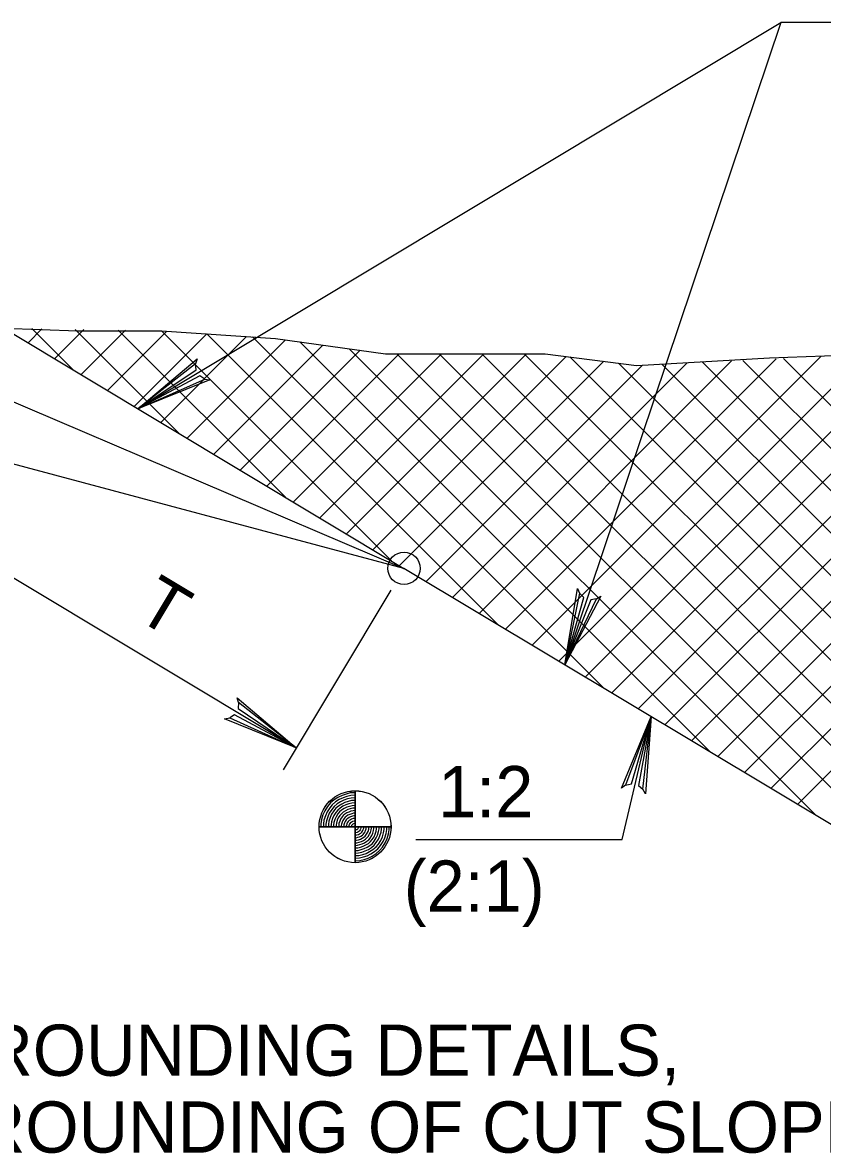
# Model space of a CAD drawing. Extents: x 240 to 1147, y 662 to 1256.
# Drawn here: x 760.7 to 810.7, y 1108.8 to 1179.4 of the extents above; entities that cross this region are included whole.
import ezdxf

# ---------------------------------------------------------------- set-up
doc = ezdxf.new("R2010")
doc.units = 0
for name, color, linetype in [('1', 7, 'Continuous'), ('2', 7, 'Continuous'), ('3', 7, 'Continuous')]:
    doc.layers.add(name, color=color, linetype=linetype)

msp = doc.modelspace()

# ---------------------------------------------------------------- linework, layer by layer
at = {"layer": '1'}
for points in [[(772.0915, 1157.151125), (771.779, 1157.346875), (767.906, 1155.301125), (772.0915, 1157.151125), (772.3955, 1157.101125), (767.906, 1155.301125), (771.53925, 1157.736375), (771.508, 1158.096875), (767.906, 1155.301125), (771.608, 1158.409375), (771.508, 1158.096875)], [(796.54975, 1143.430125), (796.183, 1143.373875), (794.56225, 1139.307375), (796.54975, 1143.430125), (796.81225, 1143.586375), (794.56225, 1139.307375), (795.74975, 1143.517625), (795.4915, 1143.771875), (794.56225, 1139.307375), (795.36425, 1144.073875), (795.4915, 1143.771875)], [(774.1955, 1136.942625), (774.1705, 1136.573875), (777.7955, 1134.117625), (774.1955, 1136.942625), (774.09775, 1137.234375), (777.7955, 1134.117625), (773.93925, 1136.180125), (773.63525, 1135.984375), (777.7955, 1134.117625), (773.31225, 1135.923875), (773.63525, 1135.984375)], [(798.36425, 1131.780125), (798.72275, 1131.869875), (799.958, 1136.069875), (798.36425, 1131.780125), (798.1165, 1131.598875), (799.958, 1136.069875), (799.1685, 1131.769875), (799.44775, 1131.538625), (799.958, 1136.069875), (799.604, 1131.251125), (799.44775, 1131.538625)]]:
    msp.add_lwpolyline(points, dxfattribs=at)
at = {"layer": '2'}
for p, q in [((784.52275, 1145.330125), (728.27275, 1160.330125)), ((759.52275, 1160.330125), (784.52275, 1145.330125)), ((761.03925, 1159.421875), (761.91025, 1160.292625)), ((763.86025, 1157.730125), (761.28725, 1160.303125)), ((762.69775, 1158.426125), (764.5185, 1160.248875)), ((770.48925, 1153.751125), (763.983, 1160.257375)), ((764.354, 1157.432375), (767.12675, 1160.205125)), ((766.01225, 1156.438625), (769.7185, 1160.144875)), ((777.1165, 1149.773875), (766.679, 1160.213625)), ((767.6685, 1155.442625), (772.204, 1159.978125)), ((783.74775, 1145.796875), (769.37475, 1160.167625)), ((790.37675, 1141.819875), (772.2185, 1159.976125)), ((769.32675, 1154.448875), (774.68725, 1159.811375)), ((770.983, 1153.455125), (777.129, 1159.601125)), ((772.6415, 1152.461375), (779.456, 1159.276125)), ((797.004, 1137.842625), (775.06225, 1159.786375)), ((803.63525, 1133.863625), (778.02275, 1159.476125)), ((807.4435, 1131.578125), (835.32475, 1159.461375)), ((809.09975, 1130.584375), (838.2685, 1159.751125)), ((774.29775, 1151.465625), (781.783, 1158.951125)), ((775.956, 1150.471875), (784.21225, 1158.728125)), ((777.61225, 1149.478125), (786.86425, 1158.728125)), ((779.2705, 1148.482375), (789.51425, 1158.728125)), ((780.92675, 1147.488625), (792.1665, 1158.728125)), ((810.26425, 1129.886375), (781.104, 1159.044875)), ((782.58525, 1146.494875), (794.654, 1158.563625)), ((816.8935, 1125.909375), (784.07275, 1158.728125)), ((823.5205, 1121.932375), (786.72475, 1158.728125)), ((827.21225, 1120.892625), (789.37675, 1158.728125)), ((829.86425, 1120.892625), (792.029, 1158.728125)), ((792.529, 1140.528125), (810.554, 1158.555125)), ((794.18525, 1139.534375), (813.33725, 1158.686375)), ((832.5165, 1120.892625), (794.87275, 1158.534375)), ((795.8435, 1138.538625), (815.97475, 1158.671875)), ((797.49975, 1137.544875), (818.5415, 1158.586375)), ((799.158, 1136.551125), (821.11025, 1158.503125)), ((805.78725, 1132.573875), (832.054, 1158.840625)), ((784.2415, 1145.498875), (797.006, 1158.265625)), ((785.89975, 1144.505125), (799.4205, 1158.026125)), ((787.556, 1143.511375), (802.204, 1158.159375)), ((789.21425, 1142.517625), (804.98725, 1158.290625)), ((790.8705, 1141.521875), (807.7705, 1158.421875)), ((835.1685, 1120.892625), (797.91025, 1158.151125)), ((837.8185, 1120.892625), (800.629, 1158.084375)), ((800.81425, 1135.555125), (823.679, 1158.419875)), ((802.47275, 1134.561375), (826.2455, 1158.336375)), ((840.4705, 1120.892625), (803.16025, 1158.203125)), ((804.129, 1133.567625), (828.81425, 1158.253125)), ((843.12275, 1120.892625), (805.6915, 1158.323875)), ((845.77475, 1120.892625), (808.22275, 1158.444875)), ((758.08525, 1156.594875), (784.52275, 1145.330125)), ((777.7955, 1134.117625), (752.7955, 1149.117625)), ((825.254, 1120.892625), (784.52275, 1145.330125)), ((783.69975, 1143.959375), (776.97275, 1132.746875)), ((781.46425, 1126.944875), (781.46425, 1131.434375)), ((781.46425, 1131.432375), (781.46425, 1126.942625)), ((781.4665, 1126.944875), (781.4665, 1131.434375)), ((781.4665, 1131.432375), (781.4665, 1126.942625)), ((783.71025, 1129.188625), (779.2185, 1129.188625)), ((783.71025, 1129.188625), (779.2185, 1129.188625)), ((779.2205, 1129.188625), (783.71025, 1129.188625)), ((779.2205, 1129.188625), (783.71025, 1129.188625))]:
    msp.add_line(p, q, dxfattribs=at)
for points in [[(767.906, 1155.301125), (808.05175, 1179.421875)], [(811.401, 1179.421875), (810.55175, 1179.421875), (808.05175, 1179.421875), (794.56225, 1139.307375)], [(759.52275, 1160.330125), (764.156, 1160.167625), (769.37675, 1160.167625), (776.4955, 1159.688625), (783.37675, 1158.728125), (793.3415, 1158.728125), (799.03725, 1158.009375), (807.3415, 1158.488625), (814.22275, 1158.728125), (820.3915, 1158.488625), (828.933, 1158.248875), (836.52675, 1159.688625), (843.1705, 1159.928125), (851.47475, 1159.448875), (864.05175, 1163.528125), (875.679, 1161.848875), (884.933, 1160.167625), (894.89775, 1159.448875), (899.406, 1159.448875), (912.2185, 1160.648875), (921.47275, 1162.328125), (925.98525, 1160.330125)], [(785.259, 1128.382375), (798.15175, 1128.382375), (799.958, 1136.069875)], [(781.458, 1131.313625), (781.1685, 1131.296875), (780.90175, 1131.228125), (780.654, 1131.148875), (780.39975, 1131.023875), (780.156, 1130.867625), (779.929, 1130.676125), (779.75175, 1130.461375), (779.57675, 1130.192625), (779.46025, 1129.930125), (779.3685, 1129.638625), (779.329, 1129.380125), (779.32475, 1129.180125)], [(781.458, 1131.155125), (781.1935, 1131.138625), (780.9455, 1131.073875), (780.71425, 1130.998875), (780.47675, 1130.884375), (780.24975, 1130.740625), (780.0415, 1130.565625), (779.881, 1130.367625), (779.7165, 1130.117625), (779.61025, 1129.873875), (779.52475, 1129.603125), (779.48925, 1129.365625), (779.48525, 1129.180125)], [(781.458, 1130.994875), (781.2185, 1130.980125), (780.9915, 1130.921875), (780.77275, 1130.851125), (780.556, 1130.744875), (780.3455, 1130.611375), (780.156, 1130.453125), (780.01025, 1130.271875), (779.858, 1130.040625), (779.76025, 1129.817625), (779.681, 1129.567625), (779.64775, 1129.351125), (779.6435, 1129.180125)], [(781.458, 1130.834375), (781.2435, 1130.821875), (781.03525, 1130.767625), (780.833, 1130.703125), (780.633, 1130.605125), (780.43925, 1130.482375), (780.2705, 1130.340625), (780.13925, 1130.178125), (779.99775, 1129.965625), (779.91025, 1129.761375), (779.83725, 1129.530125), (779.806, 1129.338625), (779.804, 1129.180125)], [(781.458, 1130.673875), (781.2685, 1130.663625), (781.079, 1130.615625), (780.8935, 1130.555125), (780.71025, 1130.467625), (780.53525, 1130.353125), (780.38525, 1130.228125), (780.2685, 1130.084375), (780.13925, 1129.888625), (780.058, 1129.705125), (779.9915, 1129.494875), (779.9665, 1129.323875), (779.96225, 1129.180125)], [(781.458, 1130.515625), (781.2935, 1130.505125), (781.12275, 1130.461375), (780.95175, 1130.405125), (780.78925, 1130.328125), (780.629, 1130.226125), (780.49975, 1130.115625), (780.3955, 1129.990625), (780.279, 1129.811375), (780.208, 1129.648875), (780.14775, 1129.457375), (780.12475, 1129.309375), (780.12275, 1129.180125)], [(781.458, 1130.355125), (781.3185, 1130.346875), (781.1665, 1130.307375), (781.01225, 1130.257375), (780.8665, 1130.188625), (780.72275, 1130.096875), (780.61225, 1130.003125), (780.52475, 1129.894875), (780.4205, 1129.736375), (780.358, 1129.592625), (780.304, 1129.421875), (780.28525, 1129.296875), (780.281, 1129.180125)], [(781.458, 1130.194875), (781.3435, 1130.188625), (781.21025, 1130.155125), (781.0705, 1130.109375), (780.9455, 1130.048875), (780.8185, 1129.967625), (780.72675, 1129.890625), (780.654, 1129.801125), (780.56025, 1129.659375), (780.508, 1129.536375), (780.46025, 1129.384375), (780.4435, 1129.282375), (780.4415, 1129.180125)], [(781.458, 1130.036375), (781.3685, 1130.030125), (781.256, 1130.001125), (781.131, 1129.961375), (781.02275, 1129.909375), (780.91225, 1129.838625), (780.8415, 1129.778125), (780.783, 1129.707375), (780.70175, 1129.582375), (780.656, 1129.480125), (780.61425, 1129.348875), (780.60175, 1129.267625), (780.59975, 1129.180125)], [(781.458, 1129.876125), (781.3915, 1129.871875), (781.29975, 1129.848875), (781.1915, 1129.813625), (781.10175, 1129.769875), (781.008, 1129.709375), (780.956, 1129.665625), (780.91225, 1129.611375), (780.8415, 1129.507375), (780.806, 1129.423875), (780.7705, 1129.311375), (780.76225, 1129.253125), (780.76025, 1129.180125)], [(781.458, 1129.715625), (781.4165, 1129.713625), (781.3435, 1129.694875), (781.24975, 1129.665625), (781.179, 1129.630125), (781.10175, 1129.582375), (781.0705, 1129.555125), (781.0415, 1129.517625), (780.983, 1129.430125), (780.956, 1129.367625), (780.92675, 1129.276125), (780.9205, 1129.240625), (780.9205, 1129.180125)], [(781.08925, 1129.188625), (781.08925, 1129.203125), (781.104, 1129.257375), (781.129, 1129.336375), (781.154, 1129.388625), (781.1935, 1129.448875), (781.204, 1129.461375), (781.22275, 1129.476125), (781.2915, 1129.521875), (781.333, 1129.540625), (781.406, 1129.563625), (781.4205, 1129.565625), (781.46425, 1129.567625)], [(781.458, 1129.394875), (781.431, 1129.388625), (781.3685, 1129.367625), (781.33525, 1129.351125), (781.29775, 1129.328125), (781.26425, 1129.278125), (781.254, 1129.257375), (781.23925, 1129.207375), (781.23925, 1129.180125)], [(781.4205, 1129.180125), (781.42275, 1129.211375), (781.42475, 1129.228125), (781.42475, 1129.230125), (781.433, 1129.238625), (781.43525, 1129.238625), (781.45175, 1129.251125), (781.45175, 1129.251125)], [(781.8415, 1129.188625), (781.8415, 1129.173875), (781.82675, 1129.119875), (781.80175, 1129.040625), (781.77675, 1128.988625), (781.73725, 1128.928125), (781.72675, 1128.915625), (781.708, 1128.901125), (781.63925, 1128.855125), (781.59775, 1128.836375), (781.52475, 1128.813625), (781.51025, 1128.811375), (781.4665, 1128.811375)], [(781.47275, 1127.063625), (781.76025, 1127.080125), (782.029, 1127.148875), (782.27675, 1127.228125), (782.531, 1127.353125), (782.77475, 1127.509375), (783.00175, 1127.698875), (783.179, 1127.915625), (783.354, 1128.182375), (783.4705, 1128.446875), (783.56025, 1128.738625), (783.60175, 1128.996875), (783.606, 1129.196875)], [(781.47275, 1127.223875), (781.73725, 1127.238625), (781.98525, 1127.303125), (782.2165, 1127.378125), (782.454, 1127.492625), (782.681, 1127.636375), (782.88925, 1127.811375), (783.04975, 1128.009375), (783.21225, 1128.259375), (783.3205, 1128.503125), (783.406, 1128.773875), (783.4415, 1129.011375), (783.4455, 1129.196875)], [(781.47275, 1127.382375), (781.71225, 1127.398875), (781.9415, 1127.455125), (782.158, 1127.526125), (782.37475, 1127.632375), (782.58525, 1127.765625), (782.77475, 1127.923875), (782.9205, 1128.105125), (783.07275, 1128.336375), (783.1705, 1128.559375), (783.24975, 1128.811375), (783.283, 1129.026125), (783.28725, 1129.196875)], [(781.47275, 1127.542625), (781.68725, 1127.555125), (781.8955, 1127.609375), (782.09775, 1127.673875), (782.29775, 1127.771875), (782.4915, 1127.894875), (782.66025, 1128.036375), (782.7915, 1128.198875), (782.933, 1128.411375), (783.0205, 1128.615625), (783.0935, 1128.846875), (783.12475, 1129.038625), (783.12675, 1129.196875)], [(781.47275, 1127.703125), (781.66225, 1127.713625), (781.85175, 1127.761375), (782.03725, 1127.821875), (782.2185, 1127.909375), (782.3955, 1128.023875), (782.5455, 1128.148875), (782.66225, 1128.292625), (782.7915, 1128.488625), (782.87275, 1128.671875), (782.93725, 1128.882375), (782.96425, 1129.053125), (782.9685, 1129.196875)], [(781.47275, 1127.861375), (781.63725, 1127.871875), (781.808, 1127.915625), (781.979, 1127.969875), (782.1415, 1128.048875), (782.30175, 1128.151125), (782.431, 1128.261375), (782.53525, 1128.386375), (782.65175, 1128.565625), (782.72275, 1128.728125), (782.783, 1128.919875), (782.806, 1129.067625), (782.808, 1129.196875)], [(781.47275, 1128.021875), (781.61225, 1128.030125), (781.76425, 1128.069875), (781.9185, 1128.119875), (782.06425, 1128.188625), (782.206, 1128.280125), (782.3165, 1128.373875), (782.406, 1128.482375), (782.51025, 1128.640625), (782.57275, 1128.784375), (782.62675, 1128.955125), (782.6455, 1129.080125), (782.64975, 1129.196875)], [(781.47275, 1128.182375), (781.58725, 1128.188625), (781.7205, 1128.221875), (781.86025, 1128.267625), (781.98525, 1128.328125), (782.11225, 1128.409375), (782.204, 1128.486375), (782.27675, 1128.576125), (782.3705, 1128.717625), (782.42275, 1128.838625), (782.4705, 1128.992625), (782.48725, 1129.094875), (782.48925, 1129.196875)], [(781.47275, 1128.340625), (781.56225, 1128.346875), (781.67475, 1128.376125), (781.79975, 1128.415625), (781.908, 1128.467625), (782.0185, 1128.538625), (782.08925, 1128.598875), (782.14775, 1128.669875), (782.229, 1128.794875), (782.27475, 1128.896875), (782.3165, 1129.028125), (782.329, 1129.109375), (782.329, 1129.196875)], [(781.47275, 1128.501125), (781.53925, 1128.505125), (781.631, 1128.528125), (781.73925, 1128.563625), (781.829, 1128.607375), (781.92275, 1128.667625), (781.97475, 1128.711375), (782.0185, 1128.765625), (782.08925, 1128.869875), (782.12475, 1128.953125), (782.16025, 1129.063625), (782.1685, 1129.123875), (782.1705, 1129.196875)], [(781.47275, 1128.661375), (781.51425, 1128.663625), (781.58725, 1128.682375), (781.681, 1128.711375), (781.75175, 1128.746875), (781.829, 1128.794875), (781.86025, 1128.823875), (781.8915, 1128.859375), (781.94775, 1128.946875), (781.97475, 1129.007375), (782.004, 1129.101125), (782.01025, 1129.136375), (782.01025, 1129.196875)], [(781.47275, 1128.982375), (781.49975, 1128.988625), (781.56225, 1129.009375), (781.5955, 1129.026125), (781.633, 1129.048875), (781.6665, 1129.098875), (781.67675, 1129.119875), (781.6915, 1129.169875), (781.6915, 1129.196875)], [(781.51025, 1129.196875), (781.508, 1129.165625), (781.506, 1129.148875), (781.504, 1129.146875), (781.49775, 1129.138625), (781.4955, 1129.136375), (781.479, 1129.126125), (781.479, 1129.126125)]]:
    msp.add_lwpolyline(points, dxfattribs=at)
for centre, radius in [((784.523167, 1145.331208), 1.015435), ((781.464512, 1129.189313), 2.24484), ((781.464512, 1129.187719), 2.24484), ((781.46617, 1129.189313), 2.24484), ((781.46617, 1129.187719), 2.24484)]:
    msp.add_circle(centre, radius, dxfattribs=at)

# ---------------------------------------------------------------- texts
at = {"layer": '1'}
msp.add_text('(2:1)', height=3.1999995, dxfattribs=at).set_placement((784.5095, 1123.882625))
at = {"layer": '2'}
msp.add_text('T', height=3.199988, rotation=329.03623889, dxfattribs=at).set_placement((767.6435, 1142.276125))
at = {"layer": '3'}
for s, height, p in [('1:2', 3.1999995, (786.654, 1129.780875)), ('FOR ROUNDING DETAILS,', 3.1999875, (748.02925, 1113.629125)), ('SEE ROUNDING OF CUT SLOPES.', 3.1999875, (748.02925, 1108.829125))]:
    msp.add_text(s, height=height, dxfattribs=at).set_placement(p)

doc.saveas('drawing.dxf')
